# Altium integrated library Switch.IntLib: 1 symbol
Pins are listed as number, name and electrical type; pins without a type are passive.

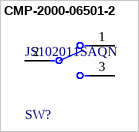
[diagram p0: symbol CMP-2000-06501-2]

## CMP-2000-06501-2
designator SW?, comment JS102011SAQN
SWITCH SLIDE SPDT 300MA 6V; Switch Function: On-On; Illumination Type: Non-Illuminated; Switch Travel: 2mm; Contact Resistance: 70mR; Actuator Material: Nylon; Electrical Life: 5000Cycles; Actuator Type: Standard
footprint FP-JS102011SAQN-MFG
pins: 1, 2 C, 3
